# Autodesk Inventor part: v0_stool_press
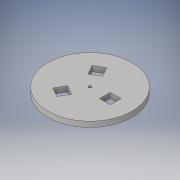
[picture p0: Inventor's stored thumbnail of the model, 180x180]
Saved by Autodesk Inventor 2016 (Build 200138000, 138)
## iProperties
Created: 2015-07
Part Number: v0_stool_press
Material: Generic
Document SubType Name: Modeling
Designer: t_patrw
Density: 1 g/cm^3
Appearance: Default
Author: t_patrw
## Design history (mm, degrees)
sketch "Sketch1"
  geometry: C1 r 142.875 at (0, 0); 1 further point
  constraints: 1 centre point, 1 coincident
  dimensions: "d0" = 285.75 diameter of C1 (= 0.75 x Seat_Diameter)
extrude "Extrusion1" new body sketch "Sketch1" distance "d1" = 18.288 (= Thickness); taper "d2" = 0 deg
sketch "Sketch2"
  geometry: C1 r 4.699 at (0, 0); 1 further point
  constraints: 1 centre point, 1 coincident
  dimensions: "d3" = 9.398 diameter of C1
extrude "Extrusion2" cut sketch "Sketch2" distance "d4" = 18.288 (= Thickness); taper "d5" = 0 deg
sketch "Sketch3"
  geometry: L1 (87.376, -18.339)-(50.8, -18.339); L2 (50.8, -18.339)-(50.8, 18.237); L3 (50.8, 18.237)-(87.376, 18.237); L4 (87.376, 18.237)-(87.376, -18.339); L5 (87.376, -18.339)-(50.8, 18.237); L6 (50.8, -18.339)-(87.376, 18.237); L7 (-9.606, -53.113)-(-27.894, -84.788); L8 (-41.282, -34.825)-(-9.606, -53.113); L9 (-27.894, -84.788)-(-59.57, -66.5); L10 (-59.57, -66.5)-(-41.282, -34.825); L11 (-41.194, 34.875)-(-59.482, 66.551); L12 (-9.518, 53.163)-(-41.194, 34.875); L13 (-59.482, 66.551)-(-27.806, 84.839); L14 (-27.806, 84.839)-(-9.518, 53.163); 2 further points
  constraints: 28 end point, 2 midpoint, 2 parallel, 1 horizontal, 1 perpendicular, 25 other
  dimensions: "d6" = 36.576 distance of L1.end L2.end (= 2 x Thickness); "d7" = 36.576 distance of L2.end L3.end (= 2 x Thickness); "d8" = 50.8 distance from line of point (0, 0) L2; "d11" = 360 deg dimension on point (0, 0) L2.end (derived)
extrude "Extrusion3" cut sketch "Sketch3" distance "d13" = 18.288 (= Thickness); taper "d14" = 0 deg
body "Solid1"
other parameters: "Thickness" = 18.288 [user parameter; used in 5 equation terms], "Height" = 457.2 [user parameter], "Seat_Diameter" = 381 [user parameter; used in 1 equation term]
